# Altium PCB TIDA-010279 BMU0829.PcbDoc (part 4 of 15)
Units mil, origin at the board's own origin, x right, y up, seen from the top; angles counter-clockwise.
Board outline 11269.69 x 4438.98 mil, 4 copper layers (Top Layer, Signal Layer 1, Signal Layer 2, Bottom Layer), stack 61.6 mil thick; 1494 components, 725 nets, 3766 pads, 2728 vias.
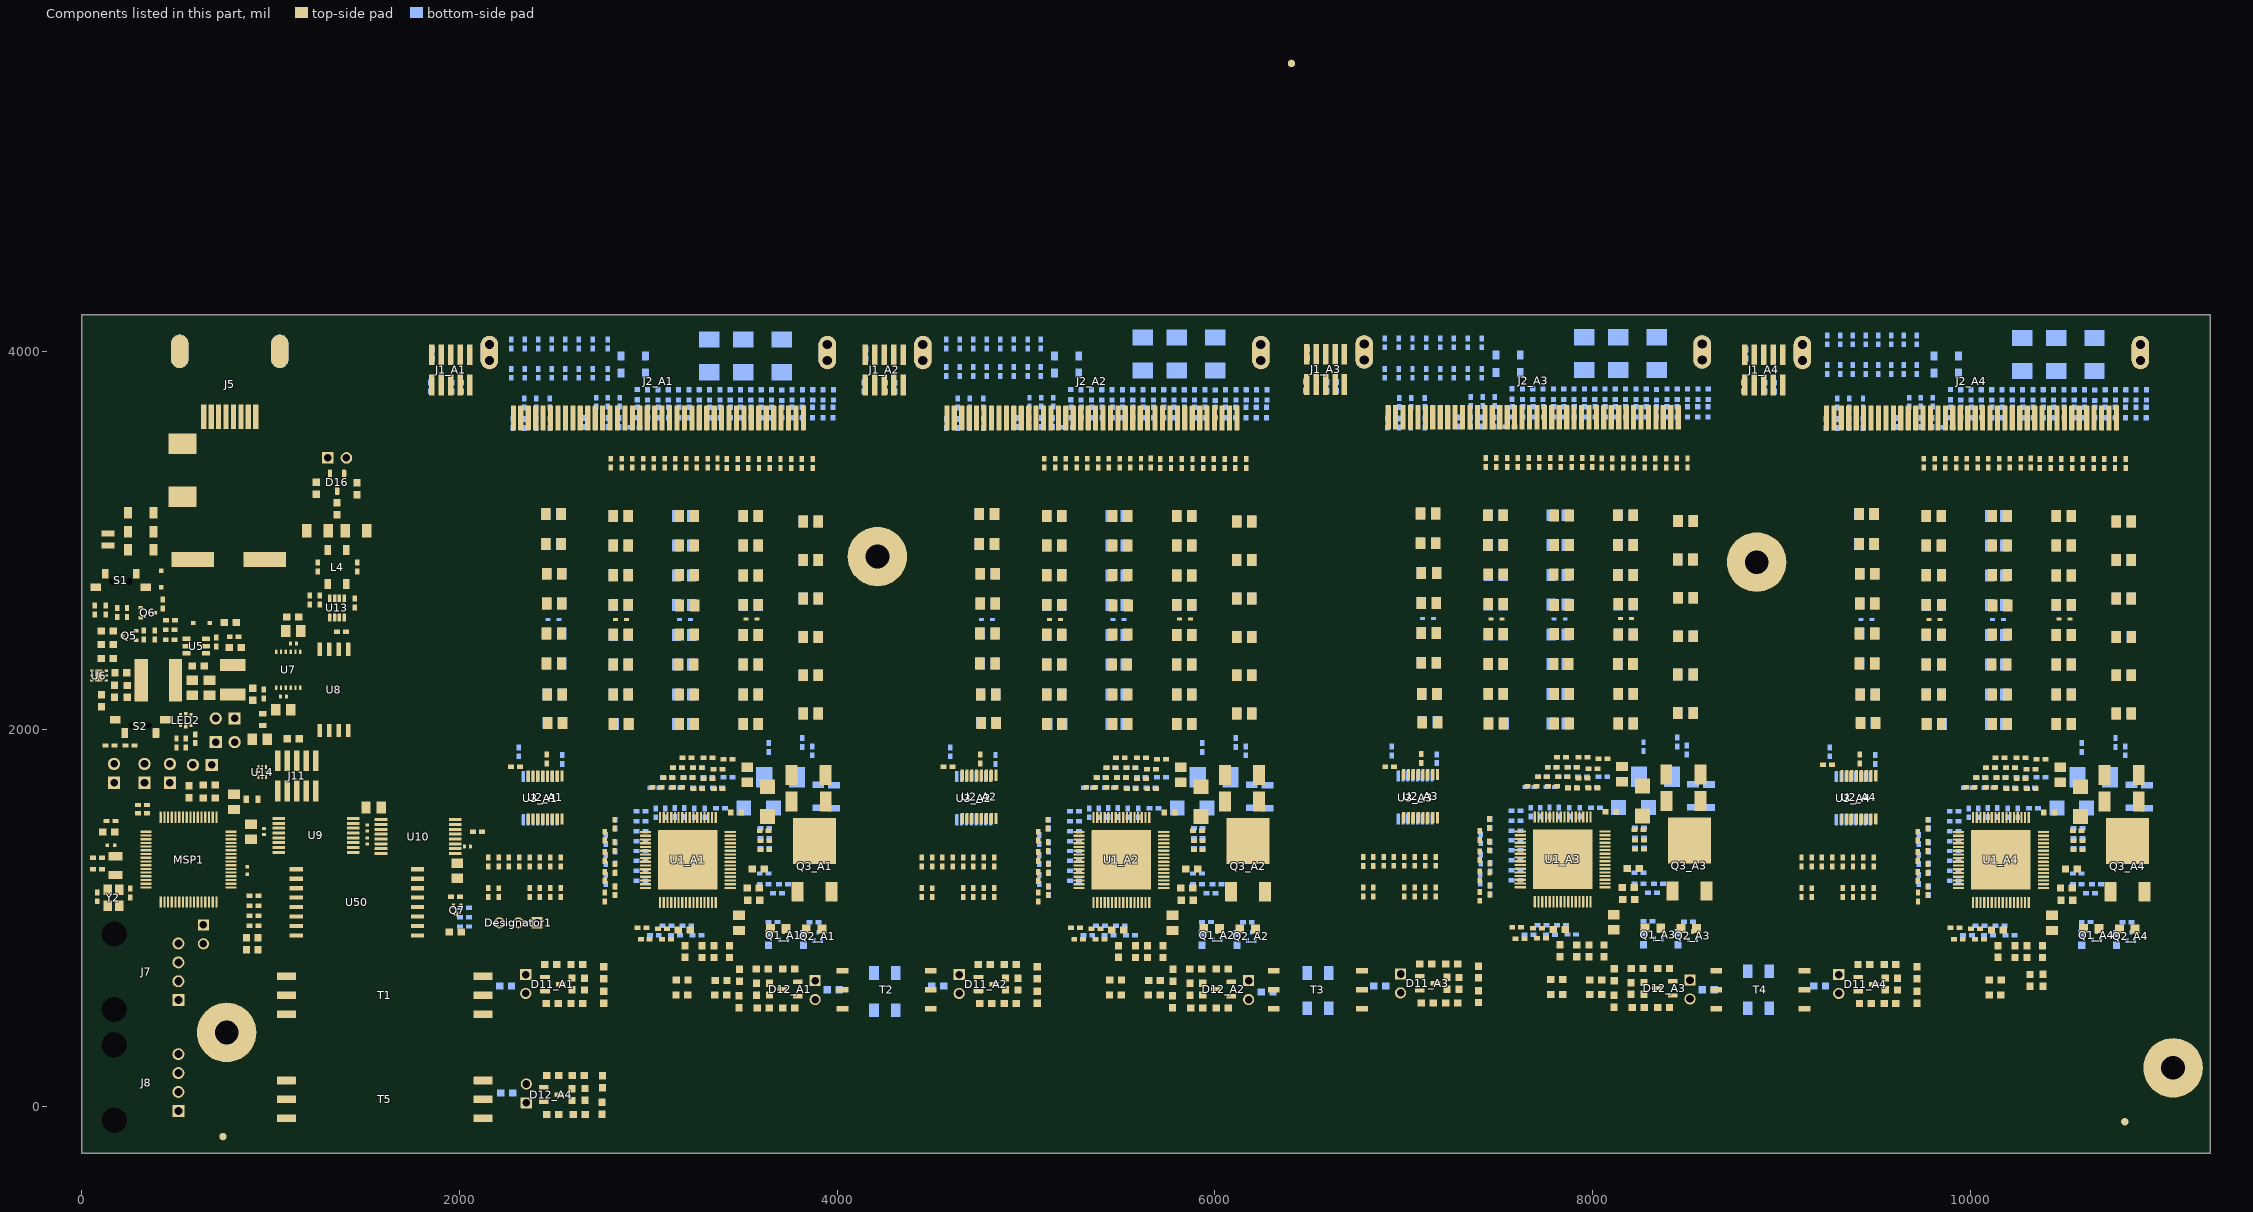
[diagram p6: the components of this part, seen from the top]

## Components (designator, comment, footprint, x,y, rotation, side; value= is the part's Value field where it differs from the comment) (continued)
R228 "CRCW0402330RJNED" 0402 501.9,1926.28 r90 top value=330
R229 "ERA-2AEB104X" FP-ERA-2AEB104X_0402-MFG 155.48,1385.02 r180 top
R230 "CRCW060310K0JNEA" 0603 134.97,2447.34 r180 top value=10k
R231 "CRCW060310K0JNEA" 0603 134.97,2519.54 r180 top value=10k
R232 "CRCW060310K0JNEA" 0603 134.37,2374.6 r180 top value=10k
R233 "CRCW040210K0JNED" 0402 328.74,2497.89 r90 top value=10k
R234 "CRCW040210K0JNED" 0402 387.5,2497.89 r90 top value=10k
R235 "CRCW04023K30JNED" 0402 127.19,2629.86 r270 top value=3.3k
R236 "CRCW0402100KJNED" 0402 188.77,2618.05 r90 top value=100k
R237 "CRCW06030000Z0EA" 0603 241.27,2199.16 r90 top value=0
R238 "CRCW06030000Z0EA" 0603 207.77,2298.46 r0 top value=0
R240 "CRCW04021K00JNED" 0402 428.12,2661.42 r270 top value=1.0k
R241 "CRCW04021K00JNED" 0402 468.51,2473.5 r0 top value=1.0k
R244 "CRCW040210K0JNED" 0402 470.48,2576.52 r180 top value=10k
R246 "CRCW060318K2FKEA" 0603 905.51,2185.04 r90 top value=18.2k
R247 "CRCW060318K2FKEA" 0603 871.88,863.32 r90 top value=18.2k
R248 "CRCW04020000Z0ED" 0402 1250.51,2857.79 r90 top value=0
R249 "ERJ-8ENF60R4V" 1206 1247.78,3050.2 r180 top value=60.4
R250 "CRCW04020000Z0ED" 0402 911.42,1011.38 r180 top value=0
R251 "CRCW04020000Z0ED" 0402 911.42,1064.2 r180 top value=0
R252 "ERJ-8ENF60R4V" 1206 1451.61,3050.2 r180 top value=60.4
R253 "CRCW04020000Z0ED" 0402 911.42,1117.02 r0 top value=0
R254 "CRCW04020000Z0ED" 0402 1457.91,2857.46 r90 top value=0
R255 "ERJ-2RKF2201X" 0402 1260.35,2683.66 r270 top value=2.20k
R256 "ERJ-2RKF2201X" 0402 1206.74,2683.66 r270 top value=2.20k
R257_A1 "CRCW0402100KFKED" 0402 3684.47,1130.99 r0 bottom value=100k (schematic designator R257)
R257_A2 "CRCW0402100KFKED" 0402 5979.48,1130.99 r0 bottom value=100k (schematic designator R257)
R257_A3 "CRCW0402100KFKED" 0402 8316.08,1134.2 r0 bottom value=100k (schematic designator R257)
R257_A4 "CRCW0402100KFKED" 0402 10636.31,1130.99 r0 bottom value=100k (schematic designator R257)
R258 "CRCW040210K0JNED" 0402 1978.35,1112.2 r0 top value=10k
RT1_A1 "TMP6131DYAT" DYA0002A-MFG 2854.78,2580.3 r180 top value=10k (schematic designator RT1)
RT1_A2 "TMP6131DYAT" DYA0002A-MFG 5153.73,2580.3 r180 top value=10k (schematic designator RT1)
RT1_A3 "TMP6131DYAT" DYA0002A-MFG 7490.33,2583.51 r180 top value=10k (schematic designator RT1)
RT1_A4 "TMP6131DYAT" DYA0002A-MFG 9810.56,2580.3 r180 top value=10k (schematic designator RT1)
RT2_A1 "TMP6131DYAT" DYA0002A-MFG 2496.83,2581.17 r0 bottom value=10k (schematic designator RT2)
RT2_A2 "TMP6131DYAT" DYA0002A-MFG 4791.85,2581.17 r0 bottom value=10k (schematic designator RT2)
RT2_A3 "TMP6131DYAT" DYA0002A-MFG 7128.44,2584.37 r0 bottom value=10k (schematic designator RT2)
RT2_A4 "TMP6131DYAT" DYA0002A-MFG 9448.67,2581.17 r0 bottom value=10k (schematic designator RT2)
RT3_A1 "TMP6131DYAT" DYA0002A-MFG 3193.75,2580.76 r0 bottom value=10k (schematic designator RT3)
RT3_A2 "TMP6131DYAT" DYA0002A-MFG 5488.77,2580.76 r0 bottom value=10k (schematic designator RT3)
RT3_A3 "TMP6131DYAT" DYA0002A-MFG 7825.36,2583.97 r0 bottom value=10k (schematic designator RT3)
RT3_A4 "TMP6131DYAT" DYA0002A-MFG 10145.59,2580.76 r0 bottom value=10k (schematic designator RT3)
RT4_A1 "TMP6131DYAT" DYA0002A-MFG 3545.43,2582.39 r180 top value=10k (schematic designator RT4)
RT4_A2 "TMP6131DYAT" DYA0002A-MFG 5840.45,2582.39 r180 top value=10k (schematic designator RT4)
RT4_A3 "TMP6131DYAT" DYA0002A-MFG 8177.04,2585.59 r180 top value=10k (schematic designator RT4)
RT4_A4 "TMP6131DYAT" DYA0002A-MFG 10497.27,2582.39 r180 top value=10k (schematic designator RT4)
S1 "1188E-1K2-V-TR" SW_1188E 206.69,2795.28 r90 top
S2 "1188E-1K2-V-TR" SW_1188E 310.26,2006.63 r270 top
T1 "LKBMT10B" FP-LKBMT10B_SMT_XFRMR_27MM9_12MM5-MFG 1604.33,590.55 r0 top
T2 "74941301" FP-HMU1228NL_SMT_TRANSFORMER_8MM89_10MM09-MFG 4261.81,620.08 r0 top
T3 "74941301" FP-HMU1228NL_SMT_TRANSFORMER_8MM89_10MM09-MFG 6545.28,620.08 r0 top
T4 "74941301" FP-HMU1228NL_SMT_TRANSFORMER_8MM89_10MM09-MFG 8887.8,620.08 r0 top
T5 "LKBMT10B" FP-LKBMT10B_SMT_XFRMR_27MM9_12MM5-MFG 1604.33,39.37 r0 top
U1_A1 "BQ78706PAP" PAP0064N-MFG 3209.47,1306.96 r270 top (schematic designator U1)
U1_A2 "BQ78706PAP" PAP0064N-MFG 5504.48,1306.96 r270 top (schematic designator U1)
U1_A3 "BQ78706PAP" PAP0064N-MFG 7841.08,1310.16 r270 top (schematic designator U1)
U1_A4 "BQ78706PAP" PAP0064N-MFG 10161.31,1306.96 r270 top (schematic designator U1)
U2_A1 "TMUX1308PWR" PW0016A-MFG 2453.51,1638.32 r90 top (schematic designator U2)
U2_A2 "TMUX1308PWR" PW0016A-MFG 4751.12,1641.67 r90 top (schematic designator U2)
U2_A3 "TMUX1308PWR" PW0016A-MFG 7088.56,1645.17 r90 top (schematic designator U2)
U2_A4 "TMUX1308PWR" PW0016A-MFG 9409.7,1638.72 r90 top (schematic designator U2)
U3_A1 "TMUX1308PWR" PW0016A-MFG 2427.92,1634.37 r90 bottom (schematic designator U3)
U3_A2 "TMUX1308PWR" PW0016A-MFG 4722.94,1634.37 r90 bottom (schematic designator U3)
U3_A3 "TMUX1308PWR" PW0016A-MFG 7059.54,1637.58 r90 bottom (schematic designator U3)
U3_A4 "TMUX1308PWR" PW0016A-MFG 9379.77,1634.37 r90 bottom (schematic designator U3)
U5 "LMR51410YDBVR" DBV0006A-MFG 606.06,2439.69 r180 top
U6 "TPS7B8133QDRVRQ1" DRV0006A 91.18,2283.19 r180 top
U7 "UCC33420" RAQ0012B-MFG 1093.51,2313.83 r90 top
U8 "ISO6721FQDWVRQ1" DWV0008A-MFG 1335.2,2207.34 r90 top
U9 "UCC33421-Q1" DWX0016A-MFG 1240.16,1437.01 r0 top
U10 "UCC33421-Q1" DWX0016A-MFG 1781.63,1430.99 r0 top
U13 "TCAN1044DDFRQ1" DDF0008A-MFG 1351.61,2641.26 r90 top
U14 "TPD6E004RSER" RSE0008A 956.6,1772.82 r270 top
U50 "ISO7831DWW" SOIC16_DWW_TEX 1456.69,1082.68 r180 top
Y1 "CM315D32768DZFT" CMHT-CM315D-2_V 179.1,1277.35 r90 top
Y2 "X1E0000210179" FP-X1E0000210179_TSX-3225-MFG 168.27,1106.97 r90 top
ZZ1 "This Assembly Note is for PCB labels only" AssemblyNoteLabel 499.96,4705.72 r0 top
ZZ2 "These assemblies are ESD sensitive, ESD precautions shall be observed." AssemblyNote 499.96,4596.83 r0 top
ZZ3 "These assemblies must be clean and free from flux and all contaminants. Use of no clean flux is not acceptable." AssemblyNote 499.96,4508.27 r0 top
ZZ4 "These assemblies must comply with workmanship standards IPC-A-610 Class 2, unless otherwise specified." AssemblyNote 499.96,4419.72 r0 top

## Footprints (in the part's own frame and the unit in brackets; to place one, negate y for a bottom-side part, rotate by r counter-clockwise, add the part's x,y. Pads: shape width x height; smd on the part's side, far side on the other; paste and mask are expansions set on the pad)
19-337_RGB [mm] "SMD, 6-Leads, Body 1.6x1.6mm"
  rect 0.55x0.4 smd: 1(-0.675,0.725) 3(-0.675,-0.725) 4(0.675,0.725) 6(0.675,-0.725)
  rect 0.7x0.5 smd: 2(-0.75,0) 5(0.75,0)
  silkscreen extent -1.2,0.6 -1.2,0.9, body extent -0.85,-0.85 0.85,0.85, height 0.35
0402 [mm] "0402 from SM-752 data"
  rect 0.8x0.6 smd: 1(-0.6,0) 2(0.6,0)
  silkscreen extent -1.22,-0.52 1.22,0.52, body extent -0.55,-0.3 0.55,0.3, height 0.6
0603 [mm] "0603 from SM-752 data"
  rect 1x0.95 smd: 1(-0.8,0) 2(0.8,0)
  silkscreen extent -1.52,-0.69 1.52,0.69, body extent -0.87,-0.47 0.87,0.47, height 1
0603_HV [mil] "Ernesto recommended land pattern.  26 mil between pads."
  rect 30x30 smd: 1(-28,0) 2(28,0)
  silkscreen extent -52,-24 52,24, body extent -34,-19 34,19, height 39
0805_HV [mil] "0805 with 30mil clearance between pads"
  rect 50x63 smd: 1(-40,0) 2(40,0)
  silkscreen extent -74,-40 74,40, body extent -43,-29 43,29, height 57
1206 [mm] "1206 from SM-752 data"
  rect 1.3x1.85 smd: 1(-1.45,0) 2(1.45,0)
  silkscreen extent -2.4,-1.21 2.4,1.21, body extent -1.7,-0.9 1.7,0.9, height 1.35
1206_180 [mm] "1206_180"
  rect 1.1x1.6 smd: 1(-1.7,0) 2(1.7,0)
  silkscreen extent -0.9,-1 0.9,1, body extent -1.75,-0.95 1.75,0.95, height 1.8
1812_280 [mm] "1812"
  rect 1.6x3.4 smd: 1(-2,0) 2(2,0)
  silkscreen extent -0.8,-1.6 0.8,1.6, body extent -2.4,-1.7 2.4,1.7, height 2.8
2010 [mm] "Chip Capacitor, Body 5.08x2.54mm, IPC Medium Density"
  rect 1.6x2.7 smd: 1(-2.3,0) 2(2.3,0)
  silkscreen extent -3.42,-1.65 3.42,1.65, body extent -2.73,-1.45 2.73,1.45, height 1.66
ACT45B_NoSilk [mm] "SMD, 4-Leads, Body 4.7 x 3.7 mm"
  rect 1.35x0.9 smd: 1(-2.275,1.25) 2(-2.275,-1.25) 3(2.275,-1.25) 4(2.275,1.25)
  body extent -2.35,-1.7 2.35,1.7, height 3
AssemblyNote [mil] "Assembly Note"
AssemblyNoteLabel [mil] "Assembly Note for PCB Labels"
Bumpon_SJ5003Transparent [mil] "3M Hemispherical Bumpon transparent"
  round 1 on Mech4: 0(0,0)
  silkscreen extent -228,-228 228,228, body extent -219,-219 219,219, height 197
CE_Mark_5mm [mil] "Minimum text height for CE Mark"
  silkscreen extent -138,-98 138,98
CMHT-CM315D-2_V [mm] "SMD, 2-Leads, Body 1.60x3.30mm, Pitch 2.50mm"
  rect 1.1x1.9 smd: 1(-1.25,0) 2(1.25,0)
  silkscreen extent -1.3,-0.8 0.3,1.32, body extent -1.65,-0.8 1.65,0.8, height 0.9
CONN_90120-0122 [mm] "Molex"
  rect 1.65x1.65 hole 1.016 mask+0: 1(-1.27,0)
  round 1.65 hole 1.016 mask+0: 2(1.27,0)
  silkscreen extent -3.56,-1.27 2.54,1.27, body extent -2.54,-1.27 2.54,1.27, height 9.29
CONN_PEC02SAAN [mm] "SULLINS"
  rrect7% 1.5x1.5 hole 1.016: 1(-1.27,0)
  round 1.5 hole 1.016: 2(1.27,0)
  silkscreen extent -2.54,-1.52 2.54,1.27, body extent -2.54,-1.27 2.54,1.27, height 8.38
CONN_PEC03SAAN [mm] "SULLINS"
  rect 1.5x1.5 hole 1.016: 1(-2.54,0)
  round 1.5 hole 1.016: 2(0,0) 3(2.54,0)
  silkscreen extent -4.72,-1.27 3.81,1.27, body extent -3.84,-1.3 3.84,1.3, height 8.38
DBV0006A-MFG [mm]
  rrect17% 1.1x0.6 smd paste+0 mask+0: 1(-1.3,0.95) 2(-1.3,0) 3(-1.3,-0.95) 4(1.3,-0.95) 5(1.3,0) 6(1.3,0.95)
  silkscreen extent -2.53,-1.53 0.35,1.53, body extent -1.95,-1.78 1.95,1.78, height 0.25
DBZ0003A-MFG [mm]
  rrect17% 1.3x0.6 smd paste+0 mask+0: 1(-1.05,0.95) 2(-1.05,-0.95) 3(1.05,0)
  silkscreen extent -0.03,-1.52 0.7,1.52, body extent -1.8,-1.62 1.8,1.62, height 0.25
DDF0008A-MFG [mm]
  rrect22% 1.05x0.45 smd paste+0 mask+0: 1(-1.3,0.975) 2(-1.3,0.325) 3(-1.3,-0.325) 4(-1.3,-0.975) 5(1.3,-0.975) 6(1.3,-0.325) 7(1.3,0.325) 8(1.3,0.975)
  silkscreen extent -2.5,-1.48 0.4,1.48, body extent -1.41,-1.45 1.41,1.45, height 1.1
DPAK [mm] "D-PAK, 3-Pads, Body 6.22x6.73mm (max), TO-252AA using nominal STEP model"
  rrect6% 2.6x1.6 smd: 1(-3.4,2.28) 3(-3.4,-2.28)
  rrect2% 6.2x5.8 smd paste-3: 2(3.4,0)
  body extent -3.86,-3.29 5.84,3.29, height 2.48
DRV0006A [mm] "SON, 6-Leads, Body 2x2mm, Pitch 0.65mm, Thermal Pad 1.6x1mm, TI Recommended"
  rrect33% 0.45x0.3 smd: 1(-0.975,0.65) 2(-0.975,0) 3(-0.975,-0.65) 4(0.975,-0.65) 5(0.975,0) 6(0.975,0.65)
  rrect14% 1x0.7 on Top Paste: 7(0,0.45) 7(0,-0.45)
  rrect10% 1x1.6 smd paste-0.5: 7(0,0)
  silkscreen extent -1.05,-1.2 1.05,1.2, body extent -1.05,-1.05 1.05,1.05, height 0.81
DWV0008A-MFG [mm]
  rrect17% 1.8x0.6 smd paste+0 mask+0: 1(-5.45,1.905) 2(-5.45,0.635) 3(-5.45,-0.635) 4(-5.45,-1.905) 5(5.45,-1.905) 6(5.45,-0.635) 7(5.45,0.635) 8(5.45,1.905)
  silkscreen extent -7.1,-2.98 3.8,2.98, body extent -6.45,-3.22 6.45,3.22, height 0.25
DWX0016A-MFG [mm]
  rrect24% 1.7x0.41 smd paste+0 mask+0: 1(-5,2.275) 2(-5,1.625) 3(-5,0.975) 4(-5,0.325) 5(-5,-0.325) 6(-5,-0.975) 7(-5,-1.625) 8(-5,-2.275) 9(5,-2.275) 10(5,-1.625) 11(5,-0.975) 12(5,-0.325) 13(5,0.325) 14(5,0.975) 15(5,1.625) 16(5,2.275)
  silkscreen extent -6.52,-2.98 3.8,2.98, body extent -5.16,-2.93 5.16,2.93, height 2.6
DYA0002A-MFG [mm]
  rrect25% 0.67x0.4 smd paste+0 mask+0: 1(-0.74,0) 2(0.74,0)
  body extent -0.8,-0.39 0.8,0.39, height 0.77
FCC_disclaimer [mil]
Fiducial10-20 [mm]
  round 1 smd mask+0.5: 1(0,0)
  Top Layer keep-out circle w1.178: c0,0 r0.5
FP-141114-210810_CONN_HDR16-MFG [mm]
  rrect14% 0.7x3.3 smd paste+0 mask+0: 1(2.5,7.7) 2(0.5,7.7) 3(-1.5,7.7) 4(-3.5,7.7) 5(3.5,7.7) 6(1.5,7.7) 7(-0.5,7.7) 8(-2.5,7.7)
  rrect100% 2.35x4.5 smd paste+0 mask+0: 9(-6.725,-1.1) 10(6.725,-1.1)
  rrect100% 2.35x4.5 smd far side paste+0 mask+0: 9(-6.725,-1.1) 10(6.725,-1.1)
  silkscreen extent -7.95,1.53 7.95,10.02, body extent -8.05,-9.3 8.05,9.45, height 0.25
FP-141114-214010_HDR40-MFG [mm]
  rrect14% 0.7x3.3 smd paste+0 mask+0: 1(18.5,7.7) 2(16.5,7.7) 3(14.5,7.7) 4(12.5,7.7) 5(10.5,7.7) 6(8.5,7.7) 7(6.5,7.7) 8(4.5,7.7) 9(2.5,7.7) 10(0.5,7.7) 11(-1.5,7.7) 12(-3.5,7.7) 13(-5.5,7.7) 14(-7.5,7.7) 15(-9.5,7.7) 16(-11.5,7.7) 17(-13.5,7.7) 18(-15.5,7.7) 19(-17.5,7.7) 20(-19.5,7.7) 21(19.5,7.7) 22(17.5,7.7) 23(15.5,7.7) 24(13.5,7.7) 25(11.5,7.7) 26(9.5,7.7) 27(7.5,7.7) 28(5.5,7.7) 29(3.5,7.7) 30(1.5,7.7) 31(-0.5,7.7) 32(-2.5,7.7) 33(-4.5,7.7) 34(-6.5,7.7) 35(-8.5,7.7) 36(-10.5,7.7) 37(-12.5,7.7) 38(-14.5,7.7) 39(-16.5,7.7) 40(-18.5,7.7)
  round 2.35 hole 1.25 paste-2539.97 mask+0: 41(-22.725,-2.175) 41(-22.725,-0.025) 42(22.725,-2.175) 42(22.725,-0.025)
  rrect100% 2.35x4.5 smd paste+0 mask+0: 41(-22.725,-1.1) 42(22.725,-1.1)
  rrect100% 2.35x4.5 smd far side paste+0 mask+0: 41(-22.725,-1.1) 42(22.725,-1.1)
  silkscreen extent -23.95,1.83 23.95,10.02, body extent -24.05,-9.3 24.05,9.45, height 0.25
FP-CGA3E2X7R2A223K080AA_0603-MFG [mm]
  rrect14% 0.7x0.7 smd paste+0 mask+0: 1(-0.7,0) 2(0.7,0)
  silkscreen extent -0.95,-0.72 0.95,0.72, body extent -0.8,-0.4 0.8,0.4, height 1.1
FP-ERA-2AEB104X_0402-MFG [mm]
  rrect21% 0.475x0.5 smd paste+0 mask+0: 1(-0.512,0) 2(0.512,0)
  silkscreen extent -0.5,-0.63 0.5,0.63, body extent -0.85,-0.4 0.85,0.4, height 0.25
FP-ERJ-2GEJ473X_0402-MFG [mm]
  rrect21% 0.475x0.5 smd paste+0 mask+0: 1(-0.512,0) 2(0.513,0)
  silkscreen extent -0.53,-0.63 0.53,0.63, body extent -0.85,-0.38 0.85,0.38, height 0.25
FP-GCM155R71H153KA55D_0402-MFG [mm]
  rrect25% 0.4x0.5 smd paste+0 mask+0: 1(-0.4,0) 2(0.4,0)
  silkscreen extent -0.53,-0.63 0.53,0.63, body extent -0.7,-0.38 0.7,0.38, height 0.25
FP-HMU1228NL_SMT_TRANSFORMER_8MM89_10MM09-MFG [mm]
  rrect13% 1.585x0.76 smd paste+0 mask+0: 1(-5.937,2.54) 2(-5.937,0) 3(-5.937,-2.54) 4(5.937,-2.54) 5(5.937,0) 6(5.937,2.54)
  silkscreen extent -7.5,-4.51 5.08,4.51, body extent -6.35,-4.44 6.35,4.44, height 6.85
FP-LKBMT10B_SMT_XFRMR_27MM9_12MM5-MFG [mm]
  rrect10% 2.55x1.02 smd paste+0 mask+0: 1(-13.225,2.54) 2(-13.225,0) 3(-13.225,-2.54) 4(13.225,-2.54) 5(13.225,0) 6(13.225,2.54)
  silkscreen extent -15.17,-6.38 14.08,6.38, body extent -15.85,-6.48 15.85,6.48, height 0.25
FP-SMD16PL-TP_SOD123FL-MFG [mm]
  rrect11% 0.91x1.22 smd paste+0 mask+0: 1(-1.635,0) 2(1.635,0)
  silkscreen extent -2.82,-0.95 0.35,0.95, body extent -1.79,-0.82 1.79,0.82, height 1.35
FP-X1E0000210179_TSX-3225-MFG [mm]
  rrect9% 1.4x1.15 smd paste+0 mask+0: 1(-1.1,-0.8) 2(1.1,-0.8) 3(1.1,0.8) 4(-1.1,0.8)
  silkscreen extent -1.22,-2.05 0,1.33, body extent -1.9,-1.48 1.9,1.48, height 0.25
Keystone_1902C [mil] "Hex Standoff, 4-40 threaded, nylon"
  round 1 on Mech4: 0(0,0)
  body extent -145,-126 146,126, height 501
Label_650x200 [mil] "Thermal Transfer Label"
  round 1 on Mech13: 0(0,0)
  silkscreen extent -325,-100 325,100, body extent -325,-100 325,100, height 1
LTST-C170KGKT_Green [mm] "LITE-ON"
  rect 1.2x1.2 smd: 1(-1.05,0) 2(1.05,0)
  silkscreen extent -1.6,-1 2.2,1, body extent -1.05,-0.67 1.05,0.67, height 1.1
Molex_70551-0038 [mm] "Header(shrouded), 2.54mm, 4x1, R/A, TH"
  rect 1.6x1.6 hole 1.09: 1(0,3.81)
  round 1.6 hole 1.09: 2(0,1.27) 3(0,-1.27) 4(0,-3.81)
  round 0 hole 3.4 unplated paste-2539.97 mask+0: MH1(8.64,-5.08) MH2(8.64,5.08)
  silkscreen extent 1.45,-6.98 12.88,7.32, body extent -0.71,-6.98 12.88,6.98, height 6.6
"NY PMS 440 0025 PH" [mm] "4-40 nylon screw and mounting hole"
  round 8 hole 3.2: 1(0,0)
  body extent -3.3,-3.3 3.3,3.3, height 2.69
Panasonic_H13 [mm] "12.5 x 13.5mm:  Panasonic H13"
  rect 5.7x2 smd: 1(-4.85,0) 2(4.85,0)
  silkscreen extent -6.85,-6.85 6.85,6.85, body extent -6.9,-6.75 6.9,6.75, height 13.5
PAP0064N-MFG [mm]
  rrect33% 1.5x0.3 smd paste+0 mask+0: 1(-5.7,3.75) 2(-5.7,3.25) 3(-5.7,2.75) 4(-5.7,2.25) 5(-5.7,1.75) 6(-5.7,1.25) 7(-5.7,0.75) 8(-5.7,0.25) 9(-5.7,-0.25) 10(-5.7,-0.75) 11(-5.7,-1.25) 12(-5.7,-1.75) 13(-5.7,-2.25) 14(-5.7,-2.75) 15(-5.7,-3.25) 16(-5.7,-3.75) 33(5.7,-3.75) 34(5.7,-3.25) 35(5.7,-2.75) 36(5.7,-2.25) 37(5.7,-1.75) 38(5.7,-1.25) 39(5.7,-0.75) 40(5.7,-0.25) 41(5.7,0.25) 42(5.7,0.75) 43(5.7,1.25) 44(5.7,1.75) 45(5.7,2.25) 46(5.7,2.75) 47(5.7,3.25) 48(5.7,3.75)
  rrect33% 0.3x1.5 smd paste+0 mask+0: 17(-3.75,-5.7) 18(-3.25,-5.7) 19(-2.75,-5.7) 20(-2.25,-5.7) 21(-1.75,-5.7) 22(-1.25,-5.7) 23(-0.75,-5.7) 24(-0.25,-5.7) 25(0.25,-5.7) 26(0.75,-5.7) 27(1.25,-5.7) 28(1.75,-5.7) 29(2.25,-5.7) 30(2.75,-5.7) 31(3.25,-5.7) 32(3.75,-5.7) 49(3.75,5.7) 50(3.25,5.7) 51(2.75,5.7) 52(2.25,5.7) 53(1.75,5.7) 54(1.25,5.7) 55(0.75,5.7) 56(0.25,5.7) 57(-0.25,5.7) 58(-0.75,5.7) 59(-1.25,5.7) 60(-1.75,5.7) 61(-2.25,5.7) 62(-2.75,5.7) 63(-3.25,5.7) 64(-3.75,5.7)
  rrect1% 8x8 smd paste-1000 mask-1000: 65(0,0)
  silkscreen extent -7.15,-5.1 5.1,5.1, body extent -6.55,-6.55 6.55,6.55, height 0.25
PM0064A-MFG [mm]
  rrect33% 1.5x0.3 smd paste+0 mask+0: 1(-5.7,3.75) 2(-5.7,3.25) 3(-5.7,2.75) 4(-5.7,2.25) 5(-5.7,1.75) 6(-5.7,1.25) 7(-5.7,0.75) 8(-5.7,0.25) 9(-5.7,-0.25) 10(-5.7,-0.75) 11(-5.7,-1.25) 12(-5.7,-1.75) 13(-5.7,-2.25) 14(-5.7,-2.75) 15(-5.7,-3.25) 16(-5.7,-3.75) 33(5.7,-3.75) 34(5.7,-3.25) 35(5.7,-2.75) 36(5.7,-2.25) 37(5.7,-1.75) 38(5.7,-1.25) 39(5.7,-0.75) 40(5.7,-0.25) 41(5.7,0.25) 42(5.7,0.75) 43(5.7,1.25) 44(5.7,1.75) 45(5.7,2.25) 46(5.7,2.75) 47(5.7,3.25) 48(5.7,3.75)
  rrect33% 0.3x1.5 smd paste+0 mask+0: 17(-3.75,-5.7) 18(-3.25,-5.7) 19(-2.75,-5.7) 20(-2.25,-5.7) 21(-1.75,-5.7) 22(-1.25,-5.7) 23(-0.75,-5.7) 24(-0.25,-5.7) 25(0.25,-5.7) 26(0.75,-5.7) 27(1.25,-5.7) 28(1.75,-5.7) 29(2.25,-5.7) 30(2.75,-5.7) 31(3.25,-5.7) 32(3.75,-5.7) 49(3.75,5.7) 50(3.25,5.7) 51(2.75,5.7) 52(2.25,5.7) 53(1.75,5.7) 54(1.25,5.7) 55(0.75,5.7) 56(0.25,5.7) 57(-0.25,5.7) 58(-0.75,5.7) 59(-1.25,5.7) 60(-1.75,5.7) 61(-2.25,5.7) 62(-2.75,5.7) 63(-3.25,5.7) 64(-3.75,5.7)
  silkscreen extent -7.13,-5.1 5.1,5.1, body extent -6.55,-6.55 6.55,6.55, height 0.25
PW0016A-MFG [mm]
  rrect22% 1.5x0.45 smd paste+0 mask+0: 1(-2.9,2.275) 2(-2.9,1.625) 3(-2.9,0.975) 4(-2.9,0.325) 5(-2.9,-0.325) 6(-2.9,-0.975) 7(-2.9,-1.625) 8(-2.9,-2.275) 9(2.9,-2.275) 10(2.9,-1.625) 11(2.9,-0.975) 12(2.9,-0.325) 13(2.9,0.325) 14(2.9,0.975) 15(2.9,1.625) 16(2.9,2.275)
  silkscreen extent -4.32,-2.55 1.78,2.55, body extent -3.2,-2.5 3.2,2.5, height 1.2
RAQ0012B-MFG [mm]
  rrect33% 0.6x0.3 smd paste+0 mask+0: 1(-2.4,1.625) 2(-2.4,0.975) 3(-2.4,0.325) 4(-2.4,-0.325) 5(-2.4,-0.975) 6(-2.4,-1.625) 7(2.4,-1.625) 8(2.4,-0.975) 9(2.4,-0.325) 10(2.4,0.325) 11(2.4,0.975) 12(2.4,1.625)
  Top Layer region: -2.65,-1.125 -2.675,-1.118 -2.693,-1.1 -2.7,-1.075 -2.7,-1.075 -2.7,-0.875 -2.696,-0.856 -2.685,-0.84 -2.669,-0.829 -2.65,-0.825 -2.65,-0.825 -2.45,-0.825 -2.431,-0.821 -2.415,-0.81 -2.404,-0.794 -2.4,-0.775 -2.4,-0.775 -2.4,-0.525 -2.404,-0.506 -2.415,-0.49 -2.431,-0.479 -2.45,-0.475 -2.45,-0.475 -2.65,-0.475 -2.675,-0.468 -2.693,-0.45 -2.7,-0.425 -2.7,-0.425 -2.7,-0.225 -2.696,-0.206 -2.685,-0.19 -2.669,-0.179 -2.65,-0.175 -2.65,-0.175 -2.45,-0.175 -2.431,-0.171 -2.415,-0.16 -2.404,-0.144 -2.4,-0.125 -2.4,-0.125 -2.4,0.125 -2.404,0.144 -2.415,0.16 -2.431,0.171 -2.45,0.175 -2.45,0.175 -2.65,0.175 -2.675,0.182 -2.693,0.2 -2.7,0.225 -2.7,0.225 -2.7,0.425 -2.693,0.45 -2.675,0.468 -2.65,0.475 -2.65,0.475 -2.15,0.475 -2.131,0.471 -2.115,0.46 -2.104,0.444 -2.1,0.425 -2.1,0.425 -2.1,-1.075 -2.104,-1.094 -2.115,-1.11 -2.131,-1.121 -2.15,-1.125 -2.15,-1.125
  Top Layer region: 2.65,-0.475 2.675,-0.468 2.693,-0.45 2.7,-0.425 2.7,-0.425 2.7,-0.225 2.696,-0.206 2.685,-0.19 2.669,-0.179 2.65,-0.175 2.65,-0.175 2.45,-0.175 2.431,-0.171 2.415,-0.16 2.404,-0.144 2.4,-0.125 2.4,-0.125 2.4,0.125 2.404,0.144 2.415,0.16 2.431,0.171 2.45,0.175 2.45,0.175 2.65,0.175 2.675,0.182 2.693,0.2 2.7,0.225 2.7,0.225 2.7,0.425 2.696,0.444 2.685,0.46 2.669,0.471 2.65,0.475 2.65,0.475 2.45,0.475 2.431,0.479 2.415,0.49 2.404,0.506 2.4,0.525 2.4,0.525 2.4,0.775 2.404,0.794 2.415,0.81 2.431,0.821 2.45,0.825 2.45,0.825 2.65,0.825 2.669,0.829 2.685,0.84 2.696,0.856 2.7,0.875 2.7,0.875 2.7,1.075 2.693,1.1 2.675,1.118 2.65,1.125 2.65,1.125 2.15,1.125 2.131,1.121 2.115,1.11 2.104,1.094 2.1,1.075 2.1,1.075 2.1,-0.425 2.104,-0.444 2.115,-0.46 2.131,-0.471 2.15,-0.475 2.15,-0.475
  silkscreen extent -3.37,-2.05 1.73,2.55, body extent -2.8,-2.15 2.8,2.15, height 0.25
RSE0008A [mm] "QFN, 8-Leads, Body 1.5x1.5mm, Pitch 0.5mm, TI Recommended"
  rrect40% 0.55x0.25 smd: 1(-0.675,0.5) 3(-0.675,-0.5) 5(0.675,-0.5) 7(0.675,0.5)
  rrect50% 0.55x0.2 smd: 2(-0.675,0) 6(0.675,0)
  rrect33% 0.3x0.6 smd: 4(0,-0.65) 8(0,0.65)
  silkscreen extent -1.02,-0.92 0.77,0.93, body extent -0.75,-0.75 0.75,0.75, height 0.6
Samtec_FTSH-105-01-x-DV-K [mm] "Header(Shrouded), 1.27mm, 5x2, SMT"
  rect 2.79x0.74 smd: 1(-2.035,2.54) 2(2.035,2.54) 3(-2.035,1.27) 4(2.035,1.27) 5(-2.035,0) 6(2.035,0) 7(-2.035,-1.27) 8(2.035,-1.27) 9(-2.035,-2.54) 10(2.035,-2.54)
  silkscreen extent -3.73,-3.48 3.73,3.48, body extent -2.92,-3.18 2.92,3.17, height 6.13
Samtec_HTSW-102-09-x-S [mm] "Header, 2x1, 2.54mm, TH"
  rect 1.55x1.55 hole 1.02: 1(-1.27,0)
  round 1.55 hole 1.02: 2(1.27,0)
  silkscreen extent -2.54,-1.24 2.54,1.6, body extent -2.54,-1.24 2.54,1.24, height 8.38
SC-89 [mm] "Vishay recommended land pattern, Document 71377 06-Jul-01"
  rect 0.66x0.38 smd: 1(-0.545,0.51) 2(-0.545,-0.51) 3(0.545,0)
  silkscreen extent 0.12,-0.97 0.63,0.97, body extent -0.85,-0.85 0.85,0.85, height 0.79
SMA [mm] "Molded Diode, 2-Leads, Body 4.3x2.6mm, IPC Medium Density, based on OnSemi component dimensions and land pattern"
  rect 2x2 smd: 1(-2,0) 2(2,0)
  silkscreen extent -3.66,-1.57 2.79,1.57, body extent -2.6,-1.3 2.6,1.3, height 2.42
SMB [mil] "Molded Diode, 2-Leads, Body 5.4x3.6mm, IPC Medium Density, based on OnSemi component dimensions"
  rect 85x107.99 smd: 1(-87.01,0) 2(87.01,0)
  silkscreen extent -155,-82 125,82, body extent -106,-71 106,71, height 91
SMC_Bi [mil] "SMC, no polarity mark"
  rect 110x150 smd: 1(-140.49,0) 2(140.49,0)
  body extent -156,-116 156,116, height 92
SOD-323 [mm] "NXP recommended land pattern"
  rect 0.6x0.6 smd paste-0.05: 1(-1.1,0) 2(1.1,0)
  silkscreen extent -2.06,-0.86 1.53,0.86, body extent -1.3,-0.67 1.3,0.68, height 1.1
SOIC16_DWW_TEX [mil]
  rect 71x22 smd paste+0 mask+0: 1(-321,175) 2(-321,125) 3(-321,75) 4(-321,25) 5(-321,-25) 6(-321,-75) 7(-321,-125) 8(-321,-175) 9(321,-175) 10(321,-125) 11(321,-75) 12(321,-25) 13(321,25) 14(321,75) 15(321,125) 16(321,175)
  silkscreen extent -282,-210 376,210, body extent -343,-204 343,204, height 104
SOT-23 [mm] "SOT23, 3-Leads, Body 2.9x1.3mm, Pitch 0.95mm, Lead Span 2.5mm, IPC Medium Density"
  rrect50% 1x0.6 smd: 1(-1.2,0.95) 2(-1.2,-0.95) 3(1.2,0)
  silkscreen extent -1.63,-1.5 0.7,1.5, body extent -1.16,-1.45 1.21,1.45, height 1
SOT-323 [mm] "Diodes Inc recommended land pattern.  2016-02-24"
  rrect21% 0.6x0.47 smd: 1(-0.95,0.65) 2(-0.95,-0.65) 3(0.95,0)
  silkscreen extent -1.14,-1.22 0.77,1.22, body extent -1.13,-1.13 1.12,1.12, height 1.13
SW_1188E [mm] "SMD, 4-Leads, Body 7.8x3.5mm"
  rrect10% 1x1.45 smd: 1(-1.1,3.375) 2(-1.1,-3.375)
  rrect11% 1.3x0.9 smd: 3(0.7,2.1) 4(0.7,-2.1)
  round 0 hole 0.9 unplated: ""(-0.35,1.15) ""(-0.35,-1.15)
  silkscreen extent -1.97,-2.28 0.95,2.28, body extent -2.55,-3.9 1.05,3.9, height 3.5
TI_Stacked_Overlay_Small [mil]
  silkscreen extent -418,-98 418,98
WCAP-CSGP_1206_L3.2W1.6H1.25 [mm] "Ceramic Capacitors, body 3.2x1.6mm"
  rect 0.9x1.6 smd: 1(-1.55,0) 2(1.55,0)
  silkscreen extent -0.8,-0.87 0.8,0.87, body extent -1.6,-0.8 1.6,0.8, height 1.25
WE-LQS_6045 [mm] "SMD Power Inductor, 2-Leads, body 6x6mm"
  rect 1.8x5.7 smd: 1(2.3,0) 2(-2.3,0)
  silkscreen extent -3.15,-3.77 3.15,3.15, body extent -3,-3 3,3, height 4.52
WE-PMCI_0806_L2W1.6H1 [mm] "Power Molded Chip Inductor, body 2x1.6mm"
  rect 0.8x1.8 smd: 1(-0.8,0) 2(0.8,0)
  body extent -1,-0.8 1,0.8, height 1
WE-PMI_0603_L1.6W0.8H0.8 [mm] "Power Multilayer Inductor, body 1.6x0.8mm"
  rect 0.7x1 smd: 1(-0.8,0) 2(0.8,0)
  body extent -0.8,-0.4 0.8,0.4, height 0.8
WEEE_Minimum [mil] "WEEElie bin"
  silkscreen extent -95,-172 99,104

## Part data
C1_A1 C1_A2 C1_A3 C1_A4 C2_A1 C2_A2 C2_A3 C2_A4 C3_A1 C3_A2 C3_A3 C3_A4 C4_A1 C4_A2 C4_A3 C4_A4 C15_A1 C15_A2 C15_A3 C15_A4 C16_A1 C16_A2 C16_A3 C16_A4 C17_A1 C17_A2 C17_A3 C17_A4 C34_A1 C34_A2 C34_A3 C34_A4 C35_A1 C35_A2 C35_A3 C35_A4 C36_A1 C36_A2 C36_A3 C36_A4 C52_A1 C52_A2 C52_A3 C52_A4 C53_A1 C53_A2 C53_A3 C53_A4 C54_A1 C54_A2 C54_A3 C54_A4 C62_A1 C62_A2 C62_A3 C62_A4 C68_A1 C68_A2 C68_A3 C68_A4 C72_A1 C72_A2 C72_A3 C72_A4 C73_A1 C73_A2 C73_A3 C73_A4 C74_A1 C74_A2 C74_A3 C74_A4 C76_A1 C76_A2 C76_A3 C76_A4 C80_A1 C80_A2 C80_A3 C80_A4 C85_A1 C85_A2 C85_A3 C85_A4 C90_A1 C90_A2 C90_A3 C90_A4 C93_A1 C93_A2 C93_A3 C93_A4 C94_A1 C94_A2 C94_A3 C94_A4 C95_A1 C95_A2 C95_A3 C95_A4 C97_A1 C97_A2 C97_A3 C97_A4 C103_A1 C103_A2 C103_A3 C103_A4 C108_A1 C108_A2 C108_A3 C108_A4 C109_A1 C109_A2 C109_A3 C109_A4 C110_A1 C110_A2 C110_A3 C110_A4 C111_A1 C111_A2 C111_A3 C111_A4 C112_A1 C112_A2 C112_A3 C112_A4 C113_A1 C113_A2 C113_A3 C113_A4 C114_A1 C114_A2 C114_A3 C114_A4 C115_A1 C115_A2 C115_A3 C115_A4 C116_A1 C116_A2 C116_A3 C116_A4 C117_A1 C117_A2 C117_A3 C117_A4 C118_A1 C118_A2 C118_A3 C118_A4 C119_A1 C119_A2 C119_A3 C119_A4 C120_A1 C120_A2 C120_A3 C120_A4 C121_A1 C121_A2 C121_A3 C121_A4 C122_A1 C122_A2 C122_A3 C122_A4 C123_A1 C123_A2 C123_A3 C123_A4 C124_A1 C124_A2 C124_A3 C124_A4 C126_A1 C126_A2 C126_A3 C126_A4 C127_A1 C127_A2 C127_A3 C127_A4 C128_A1 C128_A2 C128_A3 C128_A4 C129_A1 C129_A2 C129_A3 C129_A4 C130_A1 C130_A2 C130_A3 C130_A4 C131_A1 C131_A2 C131_A3 C131_A4 C132_A1 C132_A2 C132_A3 C132_A4 C133_A1 C133_A2 C133_A3 C133_A4 C135_A1 C135_A2 C135_A3 C135_A4 C136_A1 C136_A2 C136_A3 C136_A4 C137_A1 C137_A2 C137_A3 C137_A4 C138_A1 C138_A2 C138_A3 C138_A4 C140_A1 C140_A2 C140_A3 C140_A4 C196 C199: library part CMP-0006356-2, "CAP, CERM, 0.1 uF, 50 V, +/- 10%, X7R, AEC-Q200 Grade 1, 0402", Cap_Case=0402, Manufacturer=MuRata, Supplier Part Number 1=490-10672-1-ND, TempCo=X7R, Tolerance_%=10%, Value1=Unknown, Value2=50V, ValueDisplayed=0.1uF
C5_A1 C5_A2 C5_A3 C5_A4 C6_A1 C6_A2 C6_A3 C6_A4 C8_A1 C8_A2 C8_A3 C8_A4 C9_A1 C9_A2 C9_A3 C9_A4 C11_A1 C11_A2 C11_A3 C11_A4 C12_A1 C12_A2 C12_A3 C12_A4 C19_A1 C19_A2 C19_A3 C19_A4 C20_A1 C20_A2 C20_A3 C20_A4 C23_A1 C23_A2 C23_A3 C23_A4 C24_A1 C24_A2 C24_A3 C24_A4 C27_A1 C27_A2 C27_A3 C27_A4 C28_A1 C28_A2 C28_A3 C28_A4 C31_A1 C31_A2 C31_A3 C31_A4 C32_A1 C32_A2 C32_A3 C32_A4 C39_A1 C39_A2 C39_A3 C39_A4 C40_A1 C40_A2 C40_A3 C40_A4 C42_A1 C42_A2 C42_A3 C42_A4 C43_A1 C43_A2 C43_A3 C43_A4 C47_A1 C47_A2 C47_A3 C47_A4 C48_A1 C48_A2 C48_A3 C48_A4 C50_A1 C50_A2 C50_A3 C50_A4 C51_A1 C51_A2 C51_A3 C51_A4 C56_A1 C56_A2 C56_A3 C56_A4 C57_A1 C57_A2 C57_A3 C57_A4 C59_A1 C59_A2 C59_A3 C59_A4 C60_A1 C60_A2 C60_A3 C60_A4 C65_A1 C65_A2 C65_A3 C65_A4 C66_A1 C66_A2 C66_A3 C66_A4 C69_A1 C69_A2 C69_A3 C69_A4 C70_A1 C70_A2 C70_A3 C70_A4 C77_A1 C77_A2 C77_A3 C77_A4 C78_A1 C78_A2 C78_A3 C78_A4 C82_A1 C82_A2 C82_A3 C82_A4 C83_A1 C83_A2 C83_A3 C83_A4 C86_A1 C86_A2 C86_A3 C86_A4 C87_A1 C87_A2 C87_A3 C87_A4 C91_A1 C91_A2 C91_A3 C91_A4 C92_A1 C92_A2 C92_A3 C92_A4 C99_A1 C99_A2 C99_A3 C99_A4 C100_A1 C100_A2 C100_A3 C100_A4: library part CMP-0096840-1, "Cap Ceramic 22nF 100V X7R 10% Pad SMD 0603 +125°C Automotive T/R", Manufacturer=TDK, Operating Temperature Range="-55°C to +125°C", TempCo=0.15, Temperature Characteristic=X7R, Tolerance_%=0.1%, ValueDisplayed=22nF
C7_A1 C7_A2 C7_A3 C7_A4 C14_A1 C14_A2 C14_A3 C14_A4 C22_A1 C22_A2 C22_A3 C22_A4 C30_A1 C30_A2 C30_A3 C30_A4 C37_A1 C37_A2 C37_A3 C37_A4 C45_A1 C45_A2 C45_A3 C45_A4 C49_A1 C49_A2 C49_A3 C49_A4 C58_A1 C58_A2 C58_A3 C58_A4 C61_A1 C61_A2 C61_A3 C61_A4 C63_A1 C63_A2 C63_A3 C63_A4 C67_A1 C67_A2 C67_A3 C67_A4 C71_A1 C71_A2 C71_A3 C71_A4 C75_A1 C75_A2 C75_A3 C75_A4 C79_A1 C79_A2 C79_A3 C79_A4 C81_A1 C81_A2 C81_A3 C81_A4 C84_A1 C84_A2 C84_A3 C84_A4 C88_A1 C88_A2 C88_A3 C88_A4 C89_A1 C89_A2 C89_A3 C89_A4 C96_A1 C96_A2 C96_A3 C96_A4 C98_A1 C98_A2 C98_A3 C98_A4 C101_A1 C101_A2 C101_A3 C101_A4 C102_A1 C102_A2 C102_A3 C102_A4 C104_A1 C104_A2 C104_A3 C104_A4 C105_A1 C105_A2 C105_A3 C105_A4 C106_A1 C106_A2 C106_A3 C106_A4 C107_A1 C107_A2 C107_A3 C107_A4: library part CMP-0006361-2, "CAP, CERM, 4700 pF, 50 V, +/- 10%, X7R, AEC-Q200 Grade 1, 0402", Cap_Case=0402, Manufacturer=MuRata, Supplier Part Number 1=490-4915-1-ND, TempCo=X7R, Tolerance_%=10%, Value1=Unknown, Value2=50V, ValueDisplayed=4700pF
C18_A1 C18_A2 C18_A3 C18_A4: library part CMP-0080738-1, "CAP, CERM, 4.7 µF, 10 V,+/- 5%, X7R, AEC-Q200 Grade 1, 0805", Cap_Case=0805, Manufacturer=Kemet, Supplier Part Number 1=399-15708-1-ND, TempCo=X7R, Tolerance_%=5%, Value2=10V, ValueDisplayed=4.7µF
C26_A1 C26_A2 C26_A3 C26_A4: library part CMP-0084773-1, "CAP, CERM, 0.01 µF, 100 V,+/- 10%, X7R, AEC-Q200 Grade 1, 0603", Cap_Case=0603, Manufacturer=MuRata, TempCo=X7R, Tolerance_%=10%, Value2=100V, ValueDisplayed=0.01µF
C38_A1 C38_A2 C38_A3 C38_A4 C55_A1 C55_A2 C55_A3 C55_A4 C197: library part CMP-0007136-5, "CAP, CERM, 1 uF, 16 V, +/- 10%, X7R, AEC-Q200 Grade 1, 0603", Cap_Case=0603, Manufacturer=MuRata, Supplier Part Number 1=490-5241-6-ND, TempCo=X7R, Tolerance_%=10%, Value1=Unknown, Value2=16V, ValueDisplayed=1uF
C46_A1 C46_A2 C46_A3 C46_A4 C64_A1 C64_A2 C64_A3 C64_A4: library part CMP-0007138-4, "CAP, CERM, 0.47 uF, 16 V, +/- 10%, X7R, AEC-Q200 Grade 1, 0603", Cap_Case=0603, Manufacturer=MuRata, Supplier Part Number 1=490-4775-1-ND, TempCo=X7R, Tolerance_%=10%, Value1=Unknown, Value2=16V, ValueDisplayed=0.47uF
C125_A1 C125_A2 C125_A3 C125_A4 C191_A1 C191_A2 C191_A3 C191_A4: library part CMP-0119652-1, "WCAP-CSGP Multilayer Ceramic Chip Capacitor, General Purpose, size 1206, X7R, 100nF, 100VDC", Capacitance Tolerance=+/-10%, Case/Size Code=1206, Insulation Resistance=1GOhm, Manufacturer="Wurth Elektronik", Operating Temperature Max=125°C, Operating Temperature Min=-55°C, Rated Voltage (DC)=100V
C147_A1 C147_A2 C147_A3 C147_A4 C148_A1 C148_A2 C148_A3 C148_A4: library part CMP-0007143-4, "CAP, CERM, 0.01 uF, 50 V, +/- 10%, X7R, AEC-Q200 Grade 1, 0603", Cap_Case=0603, Manufacturer=MuRata, Supplier Part Number 1=490-4778-1-ND, TempCo=X7R, Tolerance_%=10%, Value1=Unknown, Value2=50V, ValueDisplayed=0.01uF
C149_A1 C149_A2 C149_A3 C149_A4 C150_A1 C150_A2 C150_A3 C150_A4 C151_A1 C151_A2 C151_A3 C151_A4 C152_A1 C152_A2 C152_A3 C152_A4: library part CMP-0860329-1, "CAP, CERM, 220 pF, 50 V,+/- 5%, X7R, 0603", Cap_Case=0603, Manufacturer="Samsung Electro-Mechanics", TempCo=X7R, Tolerance_%=5%, Value2=50V, ValueDisplayed=220pF
C153 C154 C155 C163 C164 C165: library part CMP-0008473-2, "CAP, CERM, 2200 pF, 100 V, +/- 5%, C0G/NP0, 1206", Cap_Case=1206, Manufacturer=AVX, Supplier Part Number 1=478-1452-1-ND, TempCo=C0G/NP0, Tolerance_%=5%, Value1="0.173 ohm", Value2=100V, ValueDisplayed=2200pF
C156 C157 C158 C159 C160 C161 C162 C166: library part CMP-0750041-1, "CAP, CERM, 100 pF, 50 V,+/- 5%, C0G/NP0, AEC-Q200 Grade 1, 0603", Cap_Case=0603, Manufacturer=MuRata, TempCo=C0G/NP0, Tolerance_%=5%, Value2=50V, ValueDisplayed=100pF
C167: library part CMP-0007304-5, "CAP, CERM, 10 uF, 6.3 V, +/- 20%, X5R, 0603", Cap_Case=0603, Manufacturer=MuRata, Supplier Part Number 1=490-7316-1-ND, TempCo=X5R, Tolerance_%=20%, Value1=Unknown, Value2=6.3V, ValueDisplayed=10uF
C168: library part CMP-0006614-2, "CAP, CERM, 0.1 uF, 50 V, +/- 20%, X5R, 0402", Cap_Case=0402, Manufacturer=MuRata, Supplier Part Number 1=GRM155R61H104ME14D-ND, TempCo=X5R, Tolerance_%=20%, Value1=Unknown, Value2=50V, ValueDisplayed=0.1uF
C169: library part CMP-0006551-2, "CAP, CERM, 0.47 uF, 6.3 V, +/- 10%, X5R, 0402", Cap_Case=0402, Manufacturer=MuRata, Supplier Part Number 1=490-3266-1-ND, TempCo=X5R, Tolerance_%=10%, Value1=Unknown, Value2=6.3V, ValueDisplayed=0.47uF
C170: library part CMP-0006614-2, "CAP, CERM, 0.1 uF, 50 V, +/- 20%, X5R, 0402", Cap_Case=0402, Manufacturer=MuRata, Supplier Part Number 1=GRM155R61H104ME14D-ND, TempCo=X5R, Tolerance_%=20%, Value1=Unknown, Value2=50V, ValueDisplayed=DNC
C171: library part CMP-0006590-2, "CAP, CERM, 0.01 uF, 16 V, +/- 10%, X5R, 0402", Cap_Case=0402, Manufacturer=MuRata, Supplier Part Number 1=GRM155R61C103KA01D-ND, TempCo=X5R, Tolerance_%=10%, Value1=Unknown, Value2=16V, ValueDisplayed=0.01uF
C172 C173: library part CMP-0007006-5, "CAP, CERM, 1 uF, 25 V, +/- 10%, X5R, 0603", Cap_Case=0603, Manufacturer=TDK, Supplier Part Number 1=445-5146-1-ND, TempCo=X5R, Tolerance_%=10%, Value1=Unknown, Value2=25V, ValueDisplayed=DNC
C174 C175 C176 C177: library part CMP-0006439-2, "CAP, CERM, 22 pF, 50 V, +/- 5%, C0G/NP0, 0402", Cap_Case=0402, Manufacturer=MuRata, Supplier Part Number 1=81-GRM1555C1H220JA1D, TempCo=C0G/NP0, Tolerance_%=5%, Value1=Unknown, Value2=50V, ValueDisplayed=22pF
C178: library part CMP-0011227-2, "CAP, AL, 47 uF, 100 V, +/- 20%, 0.42 ohm, AEC-Q200 Grade 1, SMD", Cap_Case=12.5x13.5mm, Manufacturer=Panasonic, Supplier Part Number 1=PCE3701CT-ND, Tolerance_%=20%, Value1="0.42 ohm", Value2=100V, ValueDisplayed=47uF
C179 C180 C181: library part CMP-0008724-2, "CAP, CERM, 2.2 uF, 100 V, +/- 10%, X7S, 1206", Cap_Case=1206_180, Manufacturer=TDK, Supplier Part Number 1=445-5207-1-ND, TempCo=X7S, Tolerance_%=10%, Value1="0.005718 ohm", Value2=100V, ValueDisplayed=2.2uF
C182: library part CMP-0007071-4, "CAP, CERM, 22 pF, 50 V, +/- 5%, C0G/NP0, AEC-Q200 Grade 1, 0603", Cap_Case=0603, Manufacturer=TDK, Supplier Part Number 1=445-5632-1-ND, TempCo=C0G/NP0, Tolerance_%=5%, Value1=Unknown, Value2=50V
C183: library part CMP-0008378-2, "CAP, CERM, 10 uF, 25 V, +/- 10%, X7R, 0805", Cap_Case=0805, Manufacturer=MuRata, Supplier Part Number 1=81-GRM21BZ71E106KE5L, TempCo=X7R, Tolerance_%=10%, Value1=Unknown, Value2=25V, ValueDisplayed=10uF
C184: library part CMP-0009402-2, "CAP, CERM, 22 uF, 25 V, +/- 20%, X7R, AEC-Q200 Grade 1,", Cap_Case=1812_280, Manufacturer=TDK, Supplier Part Number 1=445-7910-1-ND, TempCo=X7R, Tolerance_%=20%, Value1="0.002434 ohm", Value2=25V, ValueDisplayed=22uF
C185 C186 C189 C204 C205 C212 C213: library part CMP-0008377-2, "CAP, CERM, 22 uF, 10 V, +/- 20%, X7R, 0805", Cap_Case=0805, Manufacturer=MuRata, Supplier Part Number 1=81-GRM21BZ71A226ME5L, TempCo=X7R, Tolerance_%=20%, Value1=Unknown, Value2=10V, ValueDisplayed=22uF
C187 C190 C203 C206 C211 C214: library part CMP-0090630-1, "0.015µF ±10% 50V Ceramic Capacitor X7R 0402 (1005 Metric)", Digikey Part Number=490-11956-1-ND, Manufacturer=Murata, Mouser Part Number=81-GCM155R71H153KA5D, Operating Temperature Range="-55°C to +125°C", TempCo=15%, Temperature Characteristic=X7R, Tolerance_%=10%, ValueDisplayed=15000pF
C198: library part CMP-0081052-1, "CAP, CERM, 4.7 µF, 16 V,+/- 10%, X5R, AEC-Q200 Grade 3, 0603", Cap_Case=0603, Manufacturer=MuRata, Supplier Part Number 1=490-12319-1-ND, TempCo=X5R, Tolerance_%=10%, Value2=16V, ValueDisplayed=4.7µF
C201 C202 C216 C217 CBoot1: library part CMP-0006802-4, "CAP, CERM, 0.1 uF, 50 V, +/- 10%, X7R, 0603", Cap_Case=0603, Manufacturer=AVX, Supplier Part Number 1=478-5052-1-ND, TempCo=X7R, Tolerance_%=10%, Value1=Unknown, Value2=50V, ValueDisplayed=0.1uF
C207 C215: library part CMP-0006357-2, "CAP, CERM, 2200 pF, 50 V, +/- 10%, X7R, AEC-Q200 Grade 1, 0402", Cap_Case=0402, Manufacturer=MuRata, Supplier Part Number 1=490-4914-1-ND, TempCo=X7R, Tolerance_%=10%, Value1=Unknown, Value2=50V, ValueDisplayed=2200pF
C218 C221: library part CMP-0007129-4, "CAP, CERM, 68 pF, 50 V, +/- 5%, C0G/NP0, AEC-Q200 Grade 1, 0603", Cap_Case=0603, Manufacturer=MuRata, Supplier Part Number 1=490-4961-1-ND, TempCo=C0G/NP0, Tolerance_%=5%, Value1=Unknown, Value2=50V, ValueDisplayed=68pF
C219: library part CMP-0079247-1, "CAP, CERM, 4700 pF, 100 V,+/- 10%, X7R, AEC-Q200 Grade 1, 0603", Cap_Case=0603, Manufacturer=MuRata, Supplier Part Number 1=490-4930-1-ND, TempCo=X7R, Tolerance_%=10%, Value2=100V, ValueDisplayed=4700pF
C220 C222: library part CMP-0006350-2, "CAP, CERM, 0.1 uF, 10 V, +/- 10%, X7R, AEC-Q200 Grade 1, 0402", Cap_Case=0402, Manufacturer=MuRata, Supplier Part Number 1=81-GCM155R71A104K5D, TempCo=X7R, Tolerance_%=10%, Value1=Unknown, Value2=10V, ValueDisplayed=0.1uF
CO1: library part CMP-0007631-2, "CAP, CERM, 0.1 uF, 50 V, +/- 5%, X7R, 0805", Cap_Case=0805, Manufacturer=AVX, Supplier Part Number 1=478-3352-1-ND, TempCo=X7R, Tolerance_%=5%, Value1="0.024 ohm", Value2=50V, ValueDisplayed=0.1uF
D1_A1 D1_A2 D1_A3 D1_A4: library part CMP-0029023-2, "Diode, Superfast Rectifier, 150 V, 1 A, SMA", Manufacturer="Diodes Inc.", Value1=1A, Value2=0.92V
D2_A1 D2_A2 D2_A3 D2_A4 D3_A1 D3_A2 D3_A3 D3_A4: library part CMP-0002888-2, "LED, Green, SMD", Color=Green, Manufacturer=Lite-On, Value1=W, Value2=2V
D4_A1 D4_A2 D4_A3 D4_A4 D5_A1 D5_A2 D5_A3 D5_A4: library part CMP-0033054-1, "SMD16PL Series 60 V 1 A Surface Mount Schottky Rectifier - SOD-123FL", Digikey Part Number=SMD16PL-TPMSCT-ND, Forward Current=1A, Manufacturer="Micro Commercial Co", Max Surge Forward Current=30A, Mouser Part Number=833-SMD16PL-TP, Operating Temperature Range="-55°C to +125°C", Peak Reverse Current=0.1mA, ValueDisplayed=40pF
D6_A1 D6_A2 D6_A3 D6_A4 D7_A1 D7_A2 D7_A3 D7_A4 D8_A1 D8_A2 D8_A3 D8_A4 D10_A1 D10_A2 D10_A3 D10_A4: library part CMP-0005590-3, "Diode, TVS, Uni, 85 V, 137 Vc, SMB", Manufacturer="Diodes Inc.", Value1=600W
D9_A1 D9_A2 D9_A3 D9_A4: library part CMP-0084976-1, "Diode, TVS, Uni, 85 V, 137 Vc, 400 W, 2.9 A, SMA", Manufacturer=Littelfuse, Value1=137V
D11_A1 D11_A2 D11_A3 D11_A4 D12_A1 D12_A2 D12_A3 D12_A4: library part CMP-0122986-1, "18V two-channel bidirectional ESD protection diode", Breakdown Voltage=19V, Clamping Voltage=25V, Digikey Part Number=296-ESD652DBZRCT-ND, Manufacturer="Texas Instruments", Mouser Part Number=595-ESD652DBZR, Operating Temperature Range="-55°C to +150°C", ValueDisplayed=4pF
D13: library part CMP-0005695-3, "Diode, TVS, Bi, 33 V, SMC", Manufacturer=Littelfuse, Value1=1500W
D14 D15: library part CMP-0079597-2, "Diode, Switching, 75 V, 0.15 A, AEC-Q101, SOD-323", Manufacturer="Diodes Inc.", Value1=0.15A, Value2=1.25V
D16: library part CMP-0005919-3, "Diode, TVS, Bi, 24 V, SOT-23", Manufacturer="ON Semiconductor", Value1=350W
FID1 FID2 FID3: library part CMP-0077181-1, "Fiducial mark.  There is nothing to buy or mount.", Manufacturer=N/A
H1 H2 H3 H4: library part CMP-0003617-1, "Machine Screw, Round, #4-40 x 1/4, Nylon, Philips panhead", Manufacturer="B&F Fastener Supply", Supplier Part Number 1=H542-ND
H5 H6 H7 H8: library part CMP-0003610-1, "Standoff, Hex, 0.5\"L #4-40 Nylon", Manufacturer=Keystone, Supplier Part Number 1=36-1902C-ND
H9 H10 H11 H12: library part CMP-0003620-1, "Bumpon, Hemisphere, 0.44 X 0.20, Clear", Manufacturer=3M, Supplier Part Number 1=SJ5303-7-ND
J1_A1 J1_A2 J1_A3 J1_A4 J11: library part CMP-0075634-2, "Header(Shrouded), 1.27mm, 5x2, Gold, SMT", Color=Black, Current_A=3.3A, Manufacturer=Samtec, Supplier Part Number 1=SAM8799-ND
J2_A1 J2_A2 J2_A3 J2_A4: library part CMP-0123118-1, "2.00mm Wafer, Right Angle Connector, 40pins, Key-A With CPA Feature", Current_A=3A, Manufacturer="BEIJIDA ELECTRONICS TECHNOLOGY", Operating Temperature Range="-40°C to +125°C", Voltage_V=60V
J3_A1 J3_A2 J3_A3 J3_A4 J4_A1 J4_A2 J4_A3 J4_A4 J16: library part CMP-0002337-1, "Header, 100mil, 2x1, Tin, TH", Color=Black, Current_A=3A, Manufacturer="Sullins Connector Solutions", Supplier Part Number 1=S1012E-02-ND, Voltage_V=1.8kV
J5: library part CMP-0091530-1, "2.00mm R/A SMT WAFER 8PIN KEY-A WITH CPA FEATURE", Current_A=3A, Manufacturer="BEIJIDA ELECTRONICS TECHNOLOGY", Operating Temperature Range="-40°C to +125°C", Voltage_V=60V
J7 J8: library part CMP-0055239-1, "Header(shrouded), 2.54mm, 4x1, R/A, Gold, TH", Color=Black, Current_A=3A, Manufacturer=Molex, Supplier Part Number 1=0705510038-ND, Voltage_V=250V
J9 J12 J13 J17 J18 J20: library part CMP-0055312-1, "Header, 100mil, 2x1, Tin, TH", Manufacturer=Molex, Supplier Part Number 1=WM8072-ND
J21: library part CMP-0075626-1, "Header, 100mil, 2x1, Gold, TH", Color=Black, Manufacturer=Samtec
L2: library part CMP-0100947-1, "WE-PMCI SMT Power Molded Chip Inductor, size 0806, 1uH, 4.4A, 60mOhm", Case/Size Code=0806, DC Resistance=55mOhm, DC Resistance Max=60mOhm, Inductance=1uH, Manufacturer="Wurth Elektronik", Operating Temperature Max=125°C, Operating Temperature Min=-40°C, Rated Current=4.4A, Saturation Current=4.25A, Self Resonant Frequency=95MHz
L3: library part CMP-1354-00075-2, Ambient Temperature Range High=85°C, Ambient Temperature Range Low=-40°C, Case/Package=Nonstandard, Current Rating=1.8A, DC Resistance (DCR)=137mΩ, Inductance=33µH, Inductance Tolerance=20%, Manufacturer="Wurth Elektronik", Max DC Current=1.45A, Max Operating Temperature=125°C, Self Resonant Frequency=12MHz, Series Resistance=178.1mΩ, Test Frequency=100kHz
L4: library part CMP-0076845-1, "Coupled inductor, 51 µH, 0.2 A, 1 ohm, AEC-Q200 Grade 0, SMD", Manufacturer=TDK, Supplier Part Number 1=445-3958-1-ND, ValueDisplayed=51µH
L5 L6: library part CMP-1392-00025-2, Ambient Temperature Range High=85°C, Ambient Temperature Range Low=-40°C, Case/Package=SMD/SMT, Current Rating=550mA, DC Resistance (DCR)=300mΩ, Inductance=2.2µH, Manufacturer="Wurth Elektronik", Max Operating Temperature=125°C
LBL1: library part CMP-0003625-1, "Thermal Transfer Printable Labels, 0.650\" W x 0.200\" H - 10,000 per roll", Manufacturer=Brady, Supplier Part Number 1=97C5133
LED2: library part CMP-0074720-2, "LED, RGB, TH", Color=RGB, Manufacturer=Everlight, Value2=3.8V
Logo1: library part CMP-0074838-1, "Texas Instrument Corporate Signature"
Logo2: library part CMP-0074844-2, Manufacturer="Texas Instruments"
Logo3: library part CMP-0074847-1, "FCC_disclaimer"
Logo4: library part CMP-0074769-4, Manufacturer="Texas Instruments"
MSP1: library part CMP-0093960-1, "Mixed-Signal Microcontrollers With CAN-FD Interface LQFP64", Frequency_Fixed=80MHz, Manufacturer="Texas Instruments", Max Supply Voltage=3.6V, Min Supply Voltage=1.62V, Operating Temperature Range="-40°C to +125°C", PartNumber=MSPM0G3519SPMR
Q1_A1 Q1_A2 Q1_A3 Q1_A4 Q2_A1 Q2_A2 Q2_A3 Q2_A4 Q7: library part CMP-0086180-1, "MOSFET, N-CH, 20 V, 0.2 A, AEC-Q101, SC-89", Alternate Manufacturer=None, Manufacturer=Rohm, Value1="? ohm", Value2="? nC"
Q3_A1 Q3_A2 Q3_A3 Q3_A4: "Transistor, NPN, 150 V, 1 A, AEC-Q101, DPAK", Manufacturer="Diodes Inc.", PartNumber=ZXTN4004KTC, Value1="1 A"
Q5: library part CMP-0000013-4, "MOSFET, P-CH, -50 V, -0.15 A, AEC-Q101, SOT-323", Alternate Manufacturer=None, Manufacturer=Nexperia, Value2="0.26 nC"
Q6: library part CMP-0000486-2, "Transistor, NPN, 45 V, 0.1 A, AEC-Q101, SOT-323", Manufacturer="NXP Semiconductor", Supplier Part Number 1=568-6067-1-ND, Value1="0.1 A", Value2=800
R1_A1 R1_A2 R1_A3 R1_A4 R2_A1 R2_A2 R2_A3 R2_A4 R3_A1 R3_A2 R3_A3 R3_A4 R4_A1 R4_A2 R4_A3 R4_A4 R5_A1 R5_A2 R5_A3 R5_A4 R6_A1 R6_A2 R6_A3 R6_A4 R7_A1 R7_A2 R7_A3 R7_A4 R8_A1 R8_A2 R8_A3 R8_A4 R9_A1 R9_A2 R9_A3 R9_A4 R10_A1 R10_A2 R10_A3 R10_A4 R11_A1 R11_A2 R11_A3 R11_A4 R12_A1 R12_A2 R12_A3 R12_A4 R13_A1 R13_A2 R13_A3 R13_A4 R14_A1 R14_A2 R14_A3 R14_A4 R15_A1 R15_A2 R15_A3 R15_A4 R16_A1 R16_A2 R16_A3 R16_A4 R17_A1 R17_A2 R17_A3 R17_A4 R18_A1 R18_A2 R18_A3 R18_A4 R20_A1 R20_A2 R20_A3 R20_A4 R21_A1 R21_A2 R21_A3 R21_A4 R22_A1 R22_A2 R22_A3 R22_A4 R23_A1 R23_A2 R23_A3 R23_A4 R24_A1 R24_A2 R24_A3 R24_A4 R25_A1 R25_A2 R25_A3 R25_A4 R27_A1 R27_A2 R27_A3 R27_A4 R28_A1 R28_A2 R28_A3 R28_A4 R29_A1 R29_A2 R29_A3 R29_A4 R30_A1 R30_A2 R30_A3 R30_A4 R31_A1 R31_A2 R31_A3 R31_A4 R32_A1 R32_A2 R32_A3 R32_A4 R33_A1 R33_A2 R33_A3 R33_A4 R34_A1 R34_A2 R34_A3 R34_A4 R35_A1 R35_A2 R35_A3 R35_A4 R38_A1 R38_A2 R38_A3 R38_A4 R39_A1 R39_A2 R39_A3 R39_A4 R40_A1 R40_A2 R40_A3 R40_A4 R42_A1 R42_A2 R42_A3 R42_A4 R43_A1 R43_A2 R43_A3 R43_A4 R44_A1 R44_A2 R44_A3 R44_A4 R45_A1 R45_A2 R45_A3 R45_A4 R46_A1 R46_A2 R46_A3 R46_A4 R47_A1 R47_A2 R47_A3 R47_A4 R48_A1 R48_A2 R48_A3 R48_A4 R49_A1 R49_A2 R49_A3 R49_A4 R50_A1 R50_A2 R50_A3 R50_A4 R52_A1 R52_A2 R52_A3 R52_A4 R53_A1 R53_A2 R53_A3 R53_A4 R54_A1 R54_A2 R54_A3 R54_A4 R55_A1 R55_A2 R55_A3 R55_A4 R56_A1 R56_A2 R56_A3 R56_A4 R57_A1 R57_A2 R57_A3 R57_A4 R58_A1 R58_A2 R58_A3 R58_A4 R59_A1 R59_A2 R59_A3 R59_A4 R60_A1 R60_A2 R60_A3 R60_A4 R62_A1 R62_A2 R62_A3 R62_A4 R63_A1 R63_A2 R63_A3 R63_A4 R64_A1 R64_A2 R64_A3 R64_A4 R66_A1 R66_A2 R66_A3 R66_A4 R67_A1 R67_A2 R67_A3 R67_A4 R68_A1 R68_A2 R68_A3 R68_A4 R69_A1 R69_A2 R69_A3 R69_A4 R70_A1 R70_A2 R70_A3 R70_A4 R71_A1 R71_A2 R71_A3 R71_A4 R72_A1 R72_A2 R72_A3 R72_A4 R73_A1 R73_A2 R73_A3 R73_A4 R74_A1 R74_A2 R74_A3 R74_A4 R76_A1 R76_A2 R76_A3 R76_A4 R77_A1 R77_A2 R77_A3 R77_A4 R78_A1 R78_A2 R78_A3 R78_A4 R80_A1 R80_A2 R80_A3 R80_A4 R81_A1 R81_A2 R81_A3 R81_A4 R82_A1 R82_A2 R82_A3 R82_A4 R84_A1 R84_A2 R84_A3 R84_A4 R85_A1 R85_A2 R85_A3 R85_A4 R86_A1 R86_A2 R86_A3 R86_A4 R87_A1 R87_A2 R87_A3 R87_A4: library part CMP-0020585-3, "RES, 68, 5%, 0.125 W, AEC-Q200 Grade 0, 0805", Manufacturer=RESI, Power_W=125mW, Supplier Part Number 1=541-68ACT-ND, TempCo="200 ppm/C", Tolerance_%=5%, Value2=0.125W, Value_Code=68R0, ValueDisplayed=68
R19_A1 R19_A2 R19_A3 R19_A4 R26_A1 R26_A2 R26_A3 R26_A4 R37_A1 R37_A2 R37_A3 R37_A4 R41_A1 R41_A2 R41_A3 R41_A4 R51_A1 R51_A2 R51_A3 R51_A4 R61_A1 R61_A2 R61_A3 R61_A4 R65_A1 R65_A2 R65_A3 R65_A4 R75_A1 R75_A2 R75_A3 R75_A4 R83_A1 R83_A2 R83_A3 R83_A4 R90_A1 R90_A2 R90_A3 R90_A4 R100_A1 R100_A2 R100_A3 R100_A4 R104_A1 R104_A2 R104_A3 R104_A4 R114_A1 R114_A2 R114_A3 R114_A4 R126_A1 R126_A2 R126_A3 R126_A4 R128_A1 R128_A2 R128_A3 R128_A4 R132_A1 R132_A2 R132_A3 R132_A4 R135_A1 R135_A2 R135_A3 R135_A4 R138_A1 R138_A2 R138_A3 R138_A4 R139_A1 R139_A2 R139_A3 R139_A4: library part CMP-0026071-3, "RES, 1.00 k, 1%, 0.063 W, AEC-Q200 Grade 0, 0402", Manufacturer=Vishay-Dale, Power_W=63mW, Supplier Part Number 1=541-1.00KLCT-ND, TempCo="100 ppm/C", Tolerance_%=1%, Value2=0.063W, Value_Code=1k00, ValueDisplayed=1.00k
R36_A1 R36_A2 R36_A3 R36_A4: library part CMP-0021368-3, "RES, 60.4, 1%, 0.125 W, AEC-Q200 Grade 0, 0805", Manufacturer=Vishay-Dale, Power_W=125mW, Supplier Part Number 1=541-60.4CCT-ND, TempCo="100 ppm/C", Tolerance_%=1%, Value2=0.125W, Value_Code=60R4, ValueDisplayed=60.4
R79_A1 R79_A2 R79_A3 R79_A4: library part CMP-0026436-2, "RES, 511, 1%, 0.063 W, AEC-Q200 Grade 0, 0402", Manufacturer=Vishay-Dale, Power_W=63mW, Supplier Part Number 1=541-511LCT-ND, TempCo="100 ppm/C", Tolerance_%=1%, Value2=0.063W, Value_Code=511R, ValueDisplayed=511
R88: library part CMP-0122885-1, "47 kOhms ±5% 0.1W, 1/10W Chip Resistor 0402 (1005 Metric) Automotive AEC-Q200 Thick Film", Digikey Part Number=P47KJCT-ND, Manufacturer=Panasonic, Mouser Part Number=667-ERJ-2GEJ473X, Operating Temperature Range="-55°C to +155°C", Power=100mW, TempCo=200ppm/°C, Tolerance_%=5%
R121_A1 R121_A2 R121_A3 R121_A4 R122_A1 R122_A2 R122_A3 R122_A4 R235: library part CMP-0026918-5, "RES, 3.3 k, 5%, 0.063 W, AEC-Q200 Grade 0, 0402", Manufacturer=Vishay-Dale, Power_W=63mW, Supplier Part Number 1=541-3.3KJCT-ND, TempCo="200 ppm/C", Tolerance_%=5%, Value2=0.063W, Value_Code=3k30, ValueDisplayed=3.3k
R136_A1 R136_A2 R136_A3 R136_A4 R137_A1 R137_A2 R137_A3 R137_A4: library part CMP-0025702-4, "RES, 10 M, 5%, 0.1 W, AEC-Q200 Grade 0, 0603", Manufacturer=Vishay-Dale, Power_W=100mW, Supplier Part Number 1=541-10MGCT-ND, TempCo="200 ppm/C", Tolerance_%=5%, Value2=0.1W, Value_Code=10M0, ValueDisplayed=10M
R140_A1 R140_A2 R140_A3 R140_A4 R196_A1 R196_A2 R196_A3 R196_A4 R197_A1 R197_A2 R197_A3 R197_A4 R198_A1 R198_A2 R198_A3 R198_A4 R199_A1 R199_A2 R199_A3 R199_A4 R200_A1 R200_A2 R200_A3 R200_A4 R201_A1 R201_A2 R201_A3 R201_A4 R202_A1 R202_A2 R202_A3 R202_A4 R203_A1 R203_A2 R203_A3 R203_A4 R204_A1 R204_A2 R204_A3 R204_A4 R205_A1 R205_A2 R205_A3 R205_A4 R206_A1 R206_A2 R206_A3 R206_A4 R207_A1 R207_A2 R207_A3 R207_A4 R208 R209 R210 R211 R216 R248 R250 R251 R253 R254: library part CMP-0026822-3, "RES, 0, 5%, 0.063 W, AEC-Q200 Grade 0, 0402", Manufacturer=Vishay-Dale, Power_W=63mW, Supplier Part Number 1=541-0.0JCT-ND, TempCo="200 ppm/C", Tolerance_%=5%, Value2=0.063W, Value_Code=0000, ValueDisplayed=0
